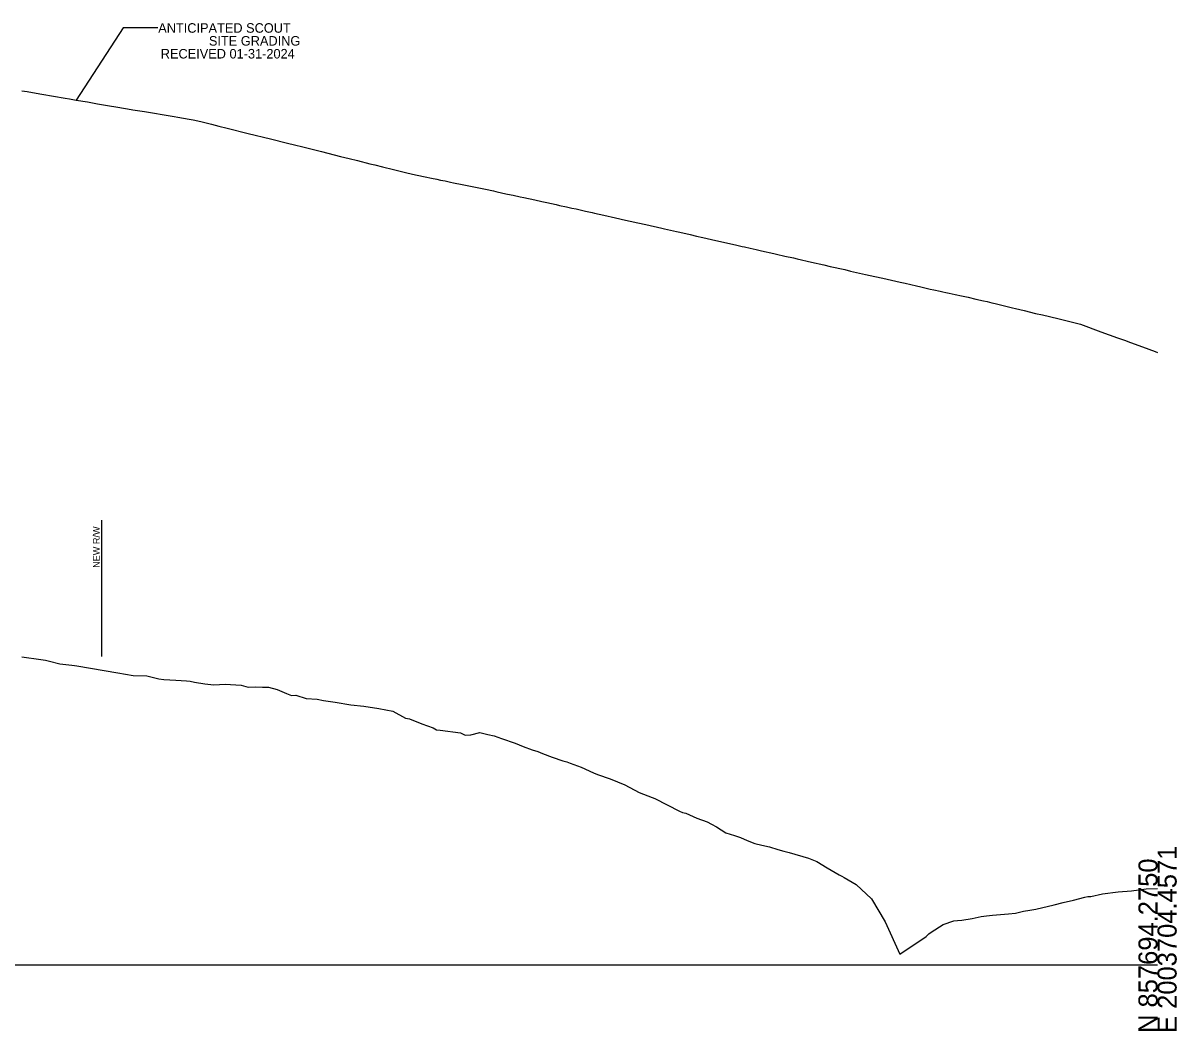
# Model space of a CAD drawing. Extents: x 2004049 to 2067449, y 841632 to 859611.
# Drawn here: x 2062280 to 2062449.4, y 857703.8 to 857851.7 of the extents above; entities that cross this region are included whole.
import ezdxf

# ---------------------------------------------------------------- set-up
doc = ezdxf.new("R2010")
doc.units = 0
for name, color, linetype in [('RD_DDB_Profile_Elev', 7, 'Continuous'), ('RD_GPK_XS_Cell', 7, 'Continuous'), ('RD_XS_ExGround', 7, 'Continuous'), ('RD_XS_TX_Box', 7, 'Continuous')]:
    doc.layers.add(name, color=color, linetype=linetype)

msp = doc.modelspace()

# ---------------------------------------------------------------- linework, layer by layer
at = {"layer": 'RD_DDB_Profile_Elev'}
for points in [[(2062299.79, 857851), (2062294.67, 857851), (2062287.82, 857840.41)], [(2062279.84, 857841.78), (2062280.62, 857841.65), (2062281.37, 857841.53), (2062282.74, 857841.29), (2062286.2, 857840.69), (2062286.84, 857840.58), (2062287.82, 857840.41), (2062289.46, 857840.13), (2062290.92, 857839.88), (2062292.97, 857839.53), (2062293.3, 857839.47), (2062295.34, 857839.13), (2062296.13, 857839), (2062297.83, 857838.71), (2062299.29, 857838.47), (2062300.41, 857838.28), (2062302.2, 857837.99), (2062302.71, 857837.9), (2062304.39, 857837.63), (2062304.99, 857837.53), (2062306.07, 857837.26), (2062307.67, 857836.86), (2062308.73, 857836.6), (2062309.95, 857836.29), (2062313.05, 857835.53), (2062316.3, 857834.72), (2062318.8, 857834.09), (2062319.84, 857833.84), (2062321.08, 857833.53), (2062323.8, 857832.85), (2062326.58, 857832.15), (2062327.87, 857831.83), (2062329.08, 857831.53), (2062330.91, 857831.07), (2062331.61, 857830.89), (2062332.75, 857830.61), (2062334.38, 857830.2), (2062335.76, 857829.86), (2062336.13, 857829.77), (2062337.14, 857829.53), (2062337.84, 857829.37), (2062339.03, 857829.13), (2062339.95, 857828.94), (2062340.71, 857828.79), (2062341.29, 857828.67), (2062341.93, 857828.54), (2062342.72, 857828.38), (2062343.19, 857828.29), (2062344.45, 857828.03), (2062345.65, 857827.79), (2062346.89, 857827.53), (2062347.88, 857827.32), (2062349.03, 857827.07), (2062349.38, 857826.99), (2062350.43, 857826.77), (2062351.11, 857826.62), (2062351.93, 857826.44), (2062352.97, 857826.22), (2062353.49, 857826.1), (2062355.11, 857825.75), (2062356.15, 857825.53), (2062356.86, 857825.37), (2062358.26, 857825.07), (2062358.74, 857824.96), (2062359.75, 857824.74), (2062360.53, 857824.57), (2062361.16, 857824.43), (2062362.14, 857824.22), (2062362.53, 857824.13), (2062363.55, 857823.9), (2062363.85, 857823.84), (2062365.24, 857823.53), (2062366.93, 857823.15), (2062368.43, 857822.81), (2062369.1, 857822.66), (2062370.21, 857822.41), (2062371.4, 857822.14), (2062373.75, 857821.61), (2062374.14, 857821.53), (2062375.93, 857821.12), (2062376.39, 857821.02), (2062377.93, 857820.67), (2062378.86, 857820.46), (2062379.76, 857820.26), (2062381.02, 857819.97), (2062382.99, 857819.53), (2062384.55, 857819.17), (2062385.53, 857818.95), (2062385.91, 857818.87), (2062386.7, 857818.69), (2062387.61, 857818.48), (2062388.39, 857818.3), (2062390.2, 857817.89), (2062390.57, 857817.81), (2062391.8, 857817.53), (2062393.08, 857817.24), (2062393.63, 857817.11), (2062395.71, 857816.64), (2062397.52, 857816.23), (2062398.47, 857816.01), (2062400.62, 857815.53), (2062401.46, 857815.33), (2062403.66, 857814.84), (2062405.02, 857814.53), (2062406.19, 857814.26), (2062408.75, 857813.69), (2062409.45, 857813.53), (2062411.15, 857813.14), (2062411.76, 857813), (2062413.16, 857812.69), (2062413.69, 857812.57), (2062414.59, 857812.37), (2062415.01, 857812.27), (2062415.42, 857812.18), (2062415.92, 857812.07), (2062416.79, 857811.88), (2062417.72, 857811.68), (2062418.72, 857811.47), (2062419.86, 857811.22), (2062420.97, 857810.97), (2062421.52, 857810.85), (2062422.21, 857810.68), (2062422.7, 857810.56), (2062424.65, 857810.08), (2062425.21, 857809.95), (2062425.66, 857809.84), (2062426.94, 857809.53), (2062428.62, 857809.12), (2062429.61, 857808.88), (2062431.86, 857808.34), (2062435.22, 857807.53), (2062438.21, 857806.42), (2062440.62, 857805.53), (2062441.64, 857805.16), (2062442.54, 857804.83), (2062444.3, 857804.19), (2062446.14, 857803.53), (2062446.51, 857803.39)]]:
    msp.add_lwpolyline(points, dxfattribs=at)
at = {"layer": 'RD_GPK_XS_Cell'}
msp.add_line((2062196.51, 857713.53), (2062446.51, 857713.53), dxfattribs=at)
at = {"layer": 'RD_XS_ExGround'}
msp.add_lwpolyline([(2062279.84, 857758.72), (2062282.63, 857758.34), (2062283.28, 857758.23), (2062283.87, 857758.09), (2062285.41, 857757.67), (2062287.14, 857757.52), (2062287.53, 857757.45), (2062287.89, 857757.4), (2062291.91, 857756.72), (2062293.91, 857756.39), (2062296.15, 857756), (2062298.16, 857755.91), (2062299.95, 857755.48), (2062300.66, 857755.39), (2062302.41, 857755.32), (2062303.98, 857755.21), (2062304.54, 857755.16), (2062305.16, 857755), (2062306.66, 857754.76), (2062308, 857754.6), (2062309.67, 857754.71), (2062312.02, 857754.54), (2062313.04, 857754.27), (2062314.17, 857754.32), (2062315.16, 857754.29), (2062316.04, 857754.28), (2062317.29, 857753.93), (2062318.68, 857753.36), (2062319.41, 857753.03), (2062320.06, 857753.12), (2062321.54, 857752.62), (2062323.18, 857752.51), (2062324.09, 857752.29), (2062325.79, 857752.05), (2062328.11, 857751.68), (2062330.04, 857751.49), (2062332.2, 857751.12), (2062334.29, 857750.76), (2062336.15, 857749.74), (2062336.7, 857749.63), (2062338.54, 857748.88), (2062340.17, 857748.28), (2062340.66, 857748.02), (2062341.21, 857747.98), (2062344.2, 857747.55), (2062344.91, 857747.23), (2062345.71, 857747.27), (2062347.04, 857747.61), (2062348.22, 857747.34), (2062349.16, 857747.15), (2062350.22, 857746.76), (2062352.24, 857746.03), (2062353.41, 857745.58), (2062354.73, 857745.1), (2062355.54, 857744.81), (2062356.26, 857744.53), (2062357.66, 857744.01), (2062359.23, 857743.47), (2062359.79, 857743.33), (2062360.28, 857743.1), (2062361.91, 857742.51), (2062363.74, 857741.69), (2062364.31, 857741.47), (2062366.16, 857740.8), (2062368.33, 857739.96), (2062370.41, 857738.82), (2062372.35, 857738.08), (2062372.75, 857737.92), (2062376.37, 857736.09), (2062376.79, 857735.87), (2062377.26, 857735.76), (2062378.91, 857735.07), (2062380.4, 857734.51), (2062381.04, 857734.15), (2062381.76, 857733.79), (2062383.16, 857732.9), (2062384.42, 857732.51), (2062385.29, 857732.22), (2062386.27, 857731.78), (2062387.41, 857731.31), (2062388.44, 857731.09), (2062389.54, 857730.83), (2062390.77, 857730.46), (2062391.66, 857730.21), (2062392.46, 857730.01), (2062395.28, 857729.19), (2062396.48, 857728.71), (2062398.04, 857727.76), (2062399.78, 857726.75), (2062400.17, 857726.54), (2062400.51, 857726.32), (2062402.29, 857725.3), (2062404.53, 857723.22), (2062406.54, 857719.82), (2062408.67, 857715.08), (2062412.57, 857717.71), (2062412.92, 857718.08), (2062413.3, 857718.31), (2062415.04, 857719.44), (2062416.59, 857719.99), (2062417.17, 857720.04), (2062417.81, 857720.1), (2062419.29, 857720.33), (2062420.62, 857720.61), (2062421.42, 857720.72), (2062422.31, 857720.8), (2062424.64, 857721.02), (2062425.67, 857721.13), (2062426.82, 857721.42), (2062427.79, 857721.53), (2062428.66, 857721.68), (2062431.33, 857722.34), (2062432.68, 857722.67), (2062434.17, 857723.02), (2062435.83, 857723.45), (2062436.29, 857723.56), (2062436.7, 857723.58), (2062438.42, 857723.95), (2062440.73, 857724.25), (2062442.67, 857724.37), (2062444.84, 857724.68), (2062446.51, 857724.75)], dxfattribs=at)
at = {"layer": 'RD_XS_TX_Box'}
msp.add_line((2062291.51, 857778.77), (2062291.51, 857758.77), dxfattribs=at)

# ---------------------------------------------------------------- texts
at = {"layer": 'RD_DDB_Profile_Elev'}
for s, p in [('ANTICIPATED SCOUT', (2062299.84, 857850.29)), ('SITE GRADING', (2062307.28, 857848.4)), ('RECEIVED 01-31-2024', (2062300.21, 857846.51))]:
    msp.add_text(s, height=1.4, dxfattribs=at).set_placement(p)
at = {"layer": 'RD_GPK_XS_Cell'}
for s, p in [('E 2003704.4571', (2062449.31, 857703.53)), ('N 857694.2750', (2062446.51, 857703.53))]:
    msp.add_text(s, height=2.8, rotation=90, dxfattribs=at).set_placement(p)
at = {"layer": 'RD_XS_TX_Box'}
msp.add_text('NEW R/W', height=1, rotation=90, dxfattribs=at).set_placement((2062291.26, 857771.77))

doc.saveas('drawing.dxf')
